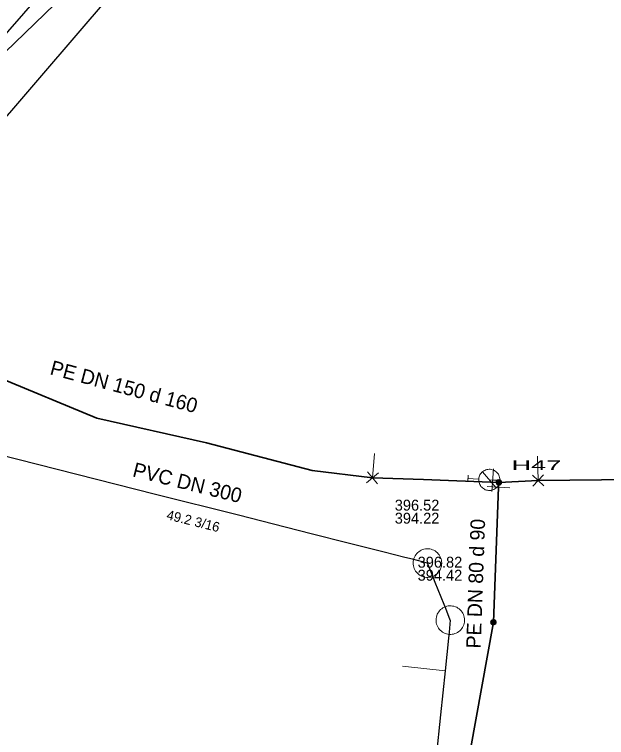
# Model space of a CAD drawing. Extents: x -772952 to -772403, y -1033777 to -1033210.
# Drawn here: x -772771.9 to -772723, y -1033366.6 to -1033306.9 of the extents above; entities that cross this region are included whole.
import ezdxf

# ---------------------------------------------------------------- set-up
doc = ezdxf.new("R2010")
doc.units = 0
doc.header["$LTSCALE"] = 0.36
for name, color, linetype, lineweight in [('15', 7, 'Continuous', 13), ('16', 7, 'Continuous', 35), ('2', 7, 'Continuous', 25), ('20', 7, 'Continuous', 13), ('4', 7, 'Continuous', 13), ('57', 7, 'Continuous', 13), ('59', 7, 'Continuous', 13)]:
    doc.layers.add(name, color=color, linetype=linetype, lineweight=lineweight)
for name, color, linetype in [('17', 7, 'Continuous'), ('3', 7, 'Continuous'), ('6', 7, 'Continuous')]:
    doc.layers.add(name, color=color, linetype=linetype)

msp = doc.modelspace()

# ---------------------------------------------------------------- linework, layer by layer
at = {"layer": '15'}
for p, q in [((-772741.867, -1033345.683), (-772742.713, -1033344.694)), ((-772732.301, -1033344.452), (-772732.438, -1033346.308)), ((-772742.779, -1033345.607), (-772741.797, -1033344.771)), ((-772728.135, -1033345.854), (-772729.082, -1033344.961)), ((-772729.05, -1033345.876), (-772728.162, -1033344.94)), ((-772730.95, -1033346.022), (-772732.81, -1033345.917))]:
    msp.add_line(p, q, dxfattribs=at)
for points in [[(-772731.619, -1033345.57), (-772731.625, -1033345.518), (-772731.642, -1033345.468), (-772731.671, -1033345.424), (-772731.708, -1033345.387), (-772731.753, -1033345.36), (-772731.803, -1033345.343), (-772731.856, -1033345.339), (-772731.907, -1033345.346), (-772731.956, -1033345.365), (-772732, -1033345.394), (-772732.036, -1033345.433), (-772732.062, -1033345.478), (-772732.078, -1033345.529), (-772732.081, -1033345.581), (-772732.073, -1033345.633), (-772732.053, -1033345.682), (-772732.022, -1033345.725), (-772731.983, -1033345.759), (-772731.937, -1033345.785), (-772731.886, -1033345.799), (-772731.833, -1033345.801), (-772731.782, -1033345.791), (-772731.733, -1033345.77), (-772731.691, -1033345.739), (-772731.657, -1033345.698), (-772731.633, -1033345.652), (-772731.62, -1033345.601)], [(-772731.649, -1033345.57), (-772731.655, -1033345.521), (-772731.672, -1033345.475), (-772731.7, -1033345.435), (-772731.737, -1033345.403), (-772731.781, -1033345.381), (-772731.829, -1033345.37), (-772731.878, -1033345.37), (-772731.924, -1033345.383), (-772731.968, -1033345.407), (-772732.004, -1033345.44), (-772732.031, -1033345.481), (-772732.047, -1033345.528), (-772732.051, -1033345.577), (-772732.044, -1033345.625), (-772732.025, -1033345.67), (-772731.995, -1033345.71), (-772731.956, -1033345.741), (-772731.913, -1033345.761), (-772731.865, -1033345.771), (-772731.816, -1033345.769), (-772731.769, -1033345.754), (-772731.726, -1033345.729), (-772731.691, -1033345.695), (-772731.666, -1033345.653), (-772731.652, -1033345.606)], [(-772731.679, -1033345.57), (-772731.684, -1033345.525), (-772731.701, -1033345.483), (-772731.73, -1033345.448), (-772731.766, -1033345.421), (-772731.808, -1033345.404), (-772731.853, -1033345.399), (-772731.897, -1033345.405), (-772731.939, -1033345.424), (-772731.973, -1033345.452), (-772732, -1033345.489), (-772732.017, -1033345.531), (-772732.021, -1033345.576), (-772732.014, -1033345.621), (-772731.995, -1033345.662), (-772731.966, -1033345.696), (-772731.929, -1033345.722), (-772731.886, -1033345.738), (-772731.841, -1033345.741), (-772731.796, -1033345.733), (-772731.755, -1033345.713), (-772731.722, -1033345.684), (-772731.696, -1033345.646), (-772731.682, -1033345.603)], [(-772731.709, -1033345.57), (-772731.713, -1033345.529), (-772731.732, -1033345.492), (-772731.759, -1033345.461), (-772731.794, -1033345.44), (-772731.834, -1033345.429), (-772731.875, -1033345.431), (-772731.914, -1033345.444), (-772731.948, -1033345.468), (-772731.973, -1033345.5), (-772731.988, -1033345.538), (-772731.99, -1033345.579), (-772731.983, -1033345.619), (-772731.963, -1033345.655), (-772731.934, -1033345.684), (-772731.897, -1033345.703), (-772731.857, -1033345.711), (-772731.816, -1033345.707), (-772731.777, -1033345.692), (-772731.745, -1033345.666), (-772731.723, -1033345.632), (-772731.71, -1033345.593)], [(-772731.739, -1033345.57), (-772731.744, -1033345.534), (-772731.762, -1033345.502), (-772731.788, -1033345.477), (-772731.821, -1033345.462), (-772731.858, -1033345.459), (-772731.892, -1033345.467), (-772731.924, -1033345.487), (-772731.946, -1033345.515), (-772731.96, -1033345.549), (-772731.96, -1033345.586), (-772731.949, -1033345.621), (-772731.928, -1033345.65), (-772731.897, -1033345.671), (-772731.863, -1033345.681), (-772731.826, -1033345.679), (-772731.792, -1033345.665), (-772731.765, -1033345.642), (-772731.745, -1033345.61), (-772731.739, -1033345.575)], [(-772731.769, -1033345.57), (-772731.774, -1033345.539), (-772731.791, -1033345.513), (-772731.816, -1033345.496), (-772731.847, -1033345.489), (-772731.878, -1033345.493), (-772731.905, -1033345.51), (-772731.923, -1033345.534), (-772731.931, -1033345.565), (-772731.927, -1033345.595), (-772731.912, -1033345.623), (-772731.887, -1033345.642), (-772731.858, -1033345.651), (-772731.826, -1033345.648), (-772731.799, -1033345.634), (-772731.779, -1033345.61), (-772731.769, -1033345.581)], [(-772731.799, -1033345.57), (-772731.804, -1033345.546), (-772731.821, -1033345.528), (-772731.843, -1033345.519), (-772731.868, -1033345.522), (-772731.889, -1033345.536), (-772731.9, -1033345.558), (-772731.9, -1033345.583), (-772731.887, -1033345.604), (-772731.868, -1033345.618), (-772731.843, -1033345.621), (-772731.82, -1033345.612), (-772731.804, -1033345.594)], [(-772731.829, -1033345.57), (-772731.834, -1033345.555), (-772731.848, -1033345.549), (-772731.864, -1033345.553), (-772731.87, -1033345.567), (-772731.867, -1033345.582), (-772731.853, -1033345.591), (-772731.838, -1033345.588), (-772731.829, -1033345.576)], [(-772732.069, -1033357.11), (-772732.075, -1033357.058), (-772732.092, -1033357.008), (-772732.121, -1033356.964), (-772732.158, -1033356.927), (-772732.203, -1033356.9), (-772732.253, -1033356.883), (-772732.306, -1033356.879), (-772732.358, -1033356.886), (-772732.407, -1033356.905), (-772732.45, -1033356.934), (-772732.486, -1033356.973), (-772732.512, -1033357.018), (-772732.528, -1033357.069), (-772732.531, -1033357.121), (-772732.523, -1033357.173), (-772732.503, -1033357.222), (-772732.472, -1033357.265), (-772732.433, -1033357.299), (-772732.387, -1033357.325), (-772732.336, -1033357.339), (-772732.283, -1033357.341), (-772732.232, -1033357.331), (-772732.184, -1033357.31), (-772732.141, -1033357.279), (-772732.107, -1033357.238), (-772732.083, -1033357.192), (-772732.071, -1033357.141)], [(-772732.099, -1033357.11), (-772732.105, -1033357.061), (-772732.122, -1033357.015), (-772732.15, -1033356.975), (-772732.187, -1033356.943), (-772732.231, -1033356.921), (-772732.279, -1033356.91), (-772732.328, -1033356.91), (-772732.375, -1033356.923), (-772732.418, -1033356.947), (-772732.454, -1033356.98), (-772732.481, -1033357.021), (-772732.497, -1033357.068), (-772732.501, -1033357.117), (-772732.494, -1033357.165), (-772732.475, -1033357.21), (-772732.445, -1033357.25), (-772732.407, -1033357.281), (-772732.363, -1033357.301), (-772732.315, -1033357.311), (-772732.266, -1033357.309), (-772732.219, -1033357.294), (-772732.176, -1033357.269), (-772732.142, -1033357.235), (-772732.116, -1033357.193), (-772732.102, -1033357.146)], [(-772732.129, -1033357.11), (-772732.135, -1033357.065), (-772732.152, -1033357.023), (-772732.18, -1033356.988), (-772732.216, -1033356.961), (-772732.258, -1033356.944), (-772732.303, -1033356.939), (-772732.348, -1033356.945), (-772732.389, -1033356.964), (-772732.424, -1033356.992), (-772732.451, -1033357.029), (-772732.467, -1033357.071), (-772732.471, -1033357.116), (-772732.464, -1033357.161), (-772732.445, -1033357.202), (-772732.416, -1033357.236), (-772732.379, -1033357.262), (-772732.336, -1033357.278), (-772732.291, -1033357.281), (-772732.246, -1033357.273), (-772732.206, -1033357.253), (-772732.172, -1033357.224), (-772732.146, -1033357.186), (-772732.132, -1033357.143)], [(-772732.159, -1033357.11), (-772732.164, -1033357.069), (-772732.182, -1033357.032), (-772732.209, -1033357.001), (-772732.244, -1033356.98), (-772732.284, -1033356.969), (-772732.325, -1033356.971), (-772732.364, -1033356.984), (-772732.398, -1033357.008), (-772732.423, -1033357.04), (-772732.438, -1033357.078), (-772732.441, -1033357.119), (-772732.433, -1033357.159), (-772732.413, -1033357.195), (-772732.384, -1033357.224), (-772732.347, -1033357.243), (-772732.307, -1033357.251), (-772732.266, -1033357.247), (-772732.228, -1033357.232), (-772732.196, -1033357.206), (-772732.173, -1033357.172), (-772732.16, -1033357.133)], [(-772732.189, -1033357.11), (-772732.194, -1033357.074), (-772732.212, -1033357.042), (-772732.238, -1033357.017), (-772732.272, -1033357.002), (-772732.308, -1033356.999), (-772732.343, -1033357.007), (-772732.374, -1033357.027), (-772732.397, -1033357.055), (-772732.41, -1033357.089), (-772732.41, -1033357.126), (-772732.399, -1033357.161), (-772732.378, -1033357.19), (-772732.348, -1033357.211), (-772732.313, -1033357.221), (-772732.276, -1033357.219), (-772732.242, -1033357.205), (-772732.215, -1033357.182), (-772732.196, -1033357.15), (-772732.189, -1033357.115)], [(-772732.219, -1033357.11), (-772732.224, -1033357.079), (-772732.241, -1033357.053), (-772732.267, -1033357.036), (-772732.297, -1033357.029), (-772732.328, -1033357.033), (-772732.355, -1033357.05), (-772732.373, -1033357.074), (-772732.381, -1033357.105), (-772732.377, -1033357.135), (-772732.362, -1033357.163), (-772732.338, -1033357.182), (-772732.308, -1033357.191), (-772732.277, -1033357.188), (-772732.249, -1033357.174), (-772732.229, -1033357.15), (-772732.219, -1033357.121)], [(-772732.249, -1033357.11), (-772732.254, -1033357.086), (-772732.271, -1033357.068), (-772732.294, -1033357.059), (-772732.318, -1033357.062), (-772732.339, -1033357.076), (-772732.35, -1033357.098), (-772732.35, -1033357.123), (-772732.338, -1033357.144), (-772732.318, -1033357.158), (-772732.293, -1033357.161), (-772732.27, -1033357.152), (-772732.254, -1033357.134)], [(-772732.279, -1033357.11), (-772732.284, -1033357.095), (-772732.299, -1033357.089), (-772732.314, -1033357.093), (-772732.321, -1033357.107), (-772732.317, -1033357.122), (-772732.304, -1033357.131), (-772732.289, -1033357.128), (-772732.279, -1033357.116)]]:
    msp.add_lwpolyline(points, close=True, dxfattribs=at)
at = {"layer": '16'}
msp.add_line((-772731.88, -1033345.97), (-772731.85, -1033345.57), dxfattribs=at)
for points in [[(-772697.486, -1033237.004), (-772702.392, -1033240.537), (-772721.486, -1033259.44), (-772724.793, -1033262.712), (-772726.954, -1033264.853), (-772730.355, -1033268.219), (-772733.767, -1033271.598), (-772743.414, -1033281.146), (-772745.156, -1033282.871), (-772753.92, -1033291.547), (-772763.164, -1033300.699), (-772765.243, -1033302.896), (-772774.291, -1033311.64)], [(-772731.85, -1033345.57), (-772738.079, -1033345.339), (-772742.289, -1033345.19), (-772747.28, -1033344.589), (-772756, -1033342.309), (-772765.059, -1033340.26), (-772773.32, -1033336.85), (-772780.26, -1033331.69), (-772786.289, -1033326.92)], [(-772731.85, -1033345.57), (-772728.609, -1033345.41), (-772720.769, -1033345.339), (-772710.35, -1033345.399), (-772705.359, -1033345.489), (-772688.94, -1033345.629), (-772678.01, -1033345.53)], [(-772752.004, -1033530.359), (-772751.19, -1033518.811), (-772750.826, -1033515.51), (-772749.541, -1033501.15), (-772748.782, -1033492.67), (-772747.697, -1033482.83), (-772745.37, -1033461.714), (-772744.103, -1033448.559), (-772744.068, -1033448.195), (-772743.857, -1033446.285), (-772742.735, -1033441.315), (-772739.627, -1033427.552), (-772737.918, -1033409.688), (-772737.464, -1033404.467), (-772736.037, -1033389.46), (-772734.688, -1033370.337), (-772732.3, -1033357.109), (-772731.88, -1033345.97)]]:
    msp.add_lwpolyline(points, dxfattribs=at)
at = {"layer": '2'}
for points in [[(-772774.26, -1033317.38), (-772766.272, -1033308.08), (-772757.691, -1033298.091), (-772754.673, -1033294.967), (-772747.614, -1033287.734), (-772737.334, -1033277.2), (-772724.53, -1033264.08)], [(-772757.63, -1033291.32), (-772758.112, -1033291.874), (-772758.373, -1033292.175), (-772759.884, -1033293.912), (-772766.704, -1033301.754), (-772767.151, -1033302.269), (-772775.095, -1033311.403), (-772775.663, -1033312.056), (-772775.897, -1033312.326), (-772776.31, -1033312.8)], [(-772737.75, -1033352.23), (-772738.982, -1033351.918), (-772739.606, -1033351.761), (-772741.329, -1033351.325), (-772744.293, -1033350.576), (-772747.353, -1033349.803), (-772750.471, -1033349.015), (-772753.362, -1033348.285), (-772760.199, -1033346.558), (-772774.838, -1033342.86), (-772775.43, -1033342.71)], [(-772735.86, -1033356.94), (-772736.243, -1033355.985), (-772736.379, -1033355.645), (-772737.109, -1033353.825), (-772737.445, -1033352.989), (-772737.75, -1033352.23)], [(-772735.86, -1033356.94), (-772735.964, -1033357.942), (-772736.014, -1033358.425), (-772736.295, -1033361.116), (-772736.676, -1033364.769), (-772737.037, -1033368.227), (-772737.417, -1033371.875), (-772737.796, -1033375.512), (-772738.174, -1033379.131), (-772738.465, -1033381.925), (-772738.512, -1033382.371), (-772738.612, -1033383.334)]]:
    msp.add_lwpolyline(points, dxfattribs=at)
at = {"layer": '20'}
for p, q in [((-772733.211, -1033344.702), (-772732.068, -1033346.028)), ((-772734.425, -1033345.504), (-772734.385, -1033344.965)), ((-772733.523, -1033345.3), (-772734.405, -1033345.235))]:
    msp.add_line(p, q, dxfattribs=at)
msp.add_lwpolyline([(-772732.575, -1033344.488), (-772732.665, -1033344.485), (-772732.756, -1033344.493), (-772732.848, -1033344.51), (-772732.934, -1033344.535), (-772733.019, -1033344.571), (-772733.1, -1033344.615), (-772733.174, -1033344.668), (-772733.245, -1033344.727), (-772733.306, -1033344.795), (-772733.362, -1033344.867), (-772733.41, -1033344.945), (-772733.45, -1033345.029), (-772733.48, -1033345.115), (-772733.501, -1033345.203), (-772733.512, -1033345.295), (-772733.514, -1033345.387), (-772733.507, -1033345.478), (-772733.49, -1033345.567), (-772733.462, -1033345.656), (-772733.426, -1033345.74), (-772733.382, -1033345.82), (-772733.332, -1033345.896), (-772733.27, -1033345.965), (-772733.205, -1033346.028), (-772733.131, -1033346.083), (-772733.052, -1033346.131), (-772732.971, -1033346.169), (-772732.883, -1033346.2), (-772732.794, -1033346.22), (-772732.703, -1033346.233), (-772732.613, -1033346.234), (-772732.522, -1033346.227), (-772732.43, -1033346.209), (-772732.344, -1033346.184), (-772732.259, -1033346.148), (-772732.178, -1033346.104), (-772732.104, -1033346.051), (-772732.033, -1033345.992), (-772731.972, -1033345.924), (-772731.916, -1033345.852), (-772731.868, -1033345.774), (-772731.828, -1033345.69), (-772731.8, -1033345.604), (-772731.777, -1033345.516), (-772731.766, -1033345.424), (-772731.764, -1033345.332), (-772731.773, -1033345.241), (-772731.788, -1033345.152), (-772731.816, -1033345.064), (-772731.852, -1033344.979), (-772731.896, -1033344.899), (-772731.946, -1033344.823), (-772732.008, -1033344.755), (-772732.073, -1033344.692), (-772732.147, -1033344.636), (-772732.226, -1033344.588), (-772732.307, -1033344.55), (-772732.395, -1033344.519), (-772732.484, -1033344.499), (-772732.573, -1033344.488)], dxfattribs=at)
at = {"layer": '4'}
for points in [[(-772736.57, -1033352.23), (-772736.576, -1033352.111), (-772736.594, -1033351.994), (-772736.623, -1033351.878), (-772736.664, -1033351.767), (-772736.716, -1033351.66), (-772736.779, -1033351.559), (-772736.852, -1033351.464), (-772736.933, -1033351.378), (-772737.023, -1033351.3), (-772737.121, -1033351.231), (-772737.224, -1033351.173), (-772737.333, -1033351.126), (-772737.447, -1033351.089), (-772737.563, -1033351.064), (-772737.681, -1033351.052), (-772737.8, -1033351.051), (-772737.919, -1033351.062), (-772738.035, -1033351.085), (-772738.149, -1033351.119), (-772738.259, -1033351.165), (-772738.364, -1033351.222), (-772738.462, -1033351.289), (-772738.553, -1033351.365), (-772738.636, -1033351.45), (-772738.71, -1033351.544), (-772738.774, -1033351.644), (-772738.828, -1033351.75), (-772738.871, -1033351.861), (-772738.903, -1033351.975), (-772738.922, -1033352.093), (-772738.93, -1033352.212), (-772738.926, -1033352.33), (-772738.91, -1033352.448), (-772738.882, -1033352.564), (-772738.843, -1033352.676), (-772738.792, -1033352.784), (-772738.731, -1033352.886), (-772738.66, -1033352.982), (-772738.58, -1033353.069), (-772738.491, -1033353.149), (-772738.395, -1033353.219), (-772738.292, -1033353.279), (-772738.184, -1033353.328), (-772738.071, -1033353.366), (-772737.955, -1033353.392), (-772737.837, -1033353.407), (-772737.718, -1033353.41), (-772737.6, -1033353.401), (-772737.482, -1033353.38), (-772737.368, -1033353.347), (-772737.258, -1033353.303), (-772737.152, -1033353.248), (-772737.053, -1033353.182), (-772736.96, -1033353.107), (-772736.876, -1033353.023), (-772736.801, -1033352.931), (-772736.735, -1033352.832), (-772736.679, -1033352.727), (-772736.635, -1033352.617), (-772736.601, -1033352.503), (-772736.58, -1033352.386), (-772736.57, -1033352.267)], [(-772734.679, -1033356.94), (-772734.686, -1033356.821), (-772734.704, -1033356.704), (-772734.733, -1033356.588), (-772734.774, -1033356.477), (-772734.826, -1033356.37), (-772734.889, -1033356.269), (-772734.962, -1033356.174), (-772735.043, -1033356.088), (-772735.133, -1033356.01), (-772735.231, -1033355.941), (-772735.334, -1033355.883), (-772735.443, -1033355.836), (-772735.557, -1033355.799), (-772735.673, -1033355.774), (-772735.791, -1033355.762), (-772735.91, -1033355.761), (-772736.029, -1033355.772), (-772736.145, -1033355.795), (-772736.259, -1033355.829), (-772736.369, -1033355.875), (-772736.473, -1033355.932), (-772736.572, -1033355.999), (-772736.663, -1033356.075), (-772736.746, -1033356.16), (-772736.82, -1033356.254), (-772736.884, -1033356.354), (-772736.938, -1033356.46), (-772736.981, -1033356.571), (-772737.013, -1033356.685), (-772737.032, -1033356.803), (-772737.04, -1033356.922), (-772737.036, -1033357.04), (-772737.02, -1033357.158), (-772736.992, -1033357.274), (-772736.953, -1033357.386), (-772736.902, -1033357.494), (-772736.841, -1033357.596), (-772736.77, -1033357.692), (-772736.69, -1033357.779), (-772736.601, -1033357.859), (-772736.505, -1033357.929), (-772736.402, -1033357.989), (-772736.294, -1033358.038), (-772736.181, -1033358.076), (-772736.065, -1033358.102), (-772735.947, -1033358.117), (-772735.828, -1033358.12), (-772735.71, -1033358.111), (-772735.592, -1033358.09), (-772735.478, -1033358.057), (-772735.368, -1033358.013), (-772735.262, -1033357.958), (-772735.163, -1033357.892), (-772735.07, -1033357.817), (-772734.986, -1033357.733), (-772734.911, -1033357.641), (-772734.845, -1033357.542), (-772734.789, -1033357.437), (-772734.745, -1033357.327), (-772734.711, -1033357.213), (-772734.69, -1033357.096), (-772734.679, -1033356.977)]]:
    msp.add_lwpolyline(points, close=True, dxfattribs=at)
at = {"layer": '57'}
msp.add_line((-772736.295, -1033361.116), (-772739.82, -1033360.75), dxfattribs=at)
at = {"layer": '59'}
for p, q in [((-772742.289, -1033345.19), (-772742.135, -1033343.193)), ((-772728.608, -1033345.41), (-772728.668, -1033343.41))]:
    msp.add_line(p, q, dxfattribs=at)
msp.add_lwpolyline([(-772731.85, -1033345.57), (-772731.84, -1033345.37), (-772732.37, -1033345.38), (-772732.64, -1033345.36)], dxfattribs=at)

# ---------------------------------------------------------------- texts
at = {"layer": '17'}
for s, rotation, p in [('PE DN 150 d 160 ', 345, (-772768.992, -1033336.625)), ('PE DN 80 d 90 ', 88, (-772733.355, -1033359.297))]:
    msp.add_text(s, height=1.2, rotation=rotation, dxfattribs=at).set_placement(p)
at = {"layer": '20', "width": 2.1}
msp.add_text('H47 ', height=0.8, dxfattribs=at).set_placement((-772730.814, -1033344.555))
at = {"layer": '3'}
for s, height, p in [('PVC DN 300', 1.2, (-772762.169, -1033345.058)), ('49.2 3/16', 0.8, (-772759.351, -1033348.602))]:
    msp.add_text(s, height=height, rotation=346, dxfattribs=at).set_placement(p)
at = {"layer": '6'}
for s, p in [('396.52', (-772740.448, -1033347.897)), ('394.22', (-772740.448, -1033348.974)), ('396.82', (-772738.558, -1033352.607)), ('394.42', (-772738.558, -1033353.684))]:
    msp.add_text(s, height=0.9, dxfattribs=at).set_placement(p)

doc.saveas('drawing.dxf')
